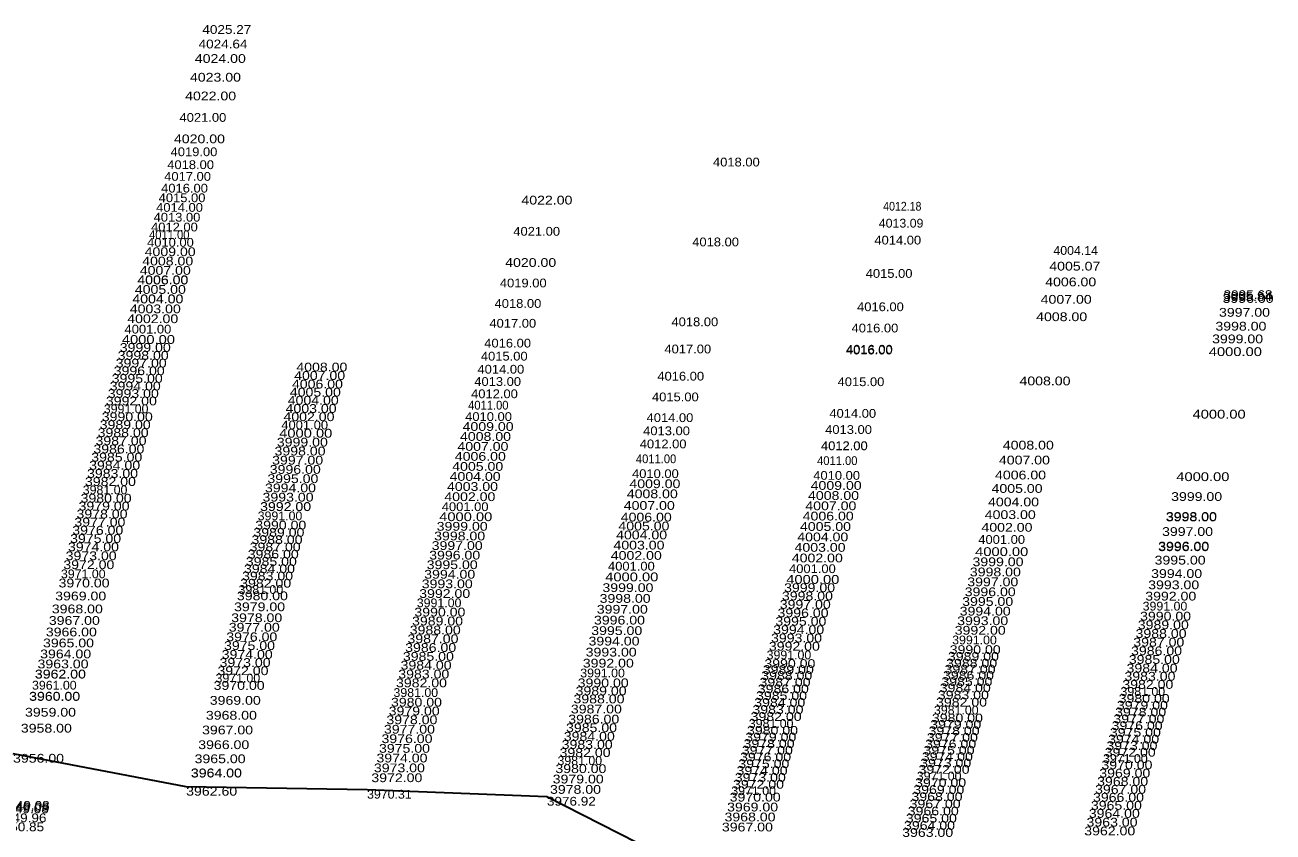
# Model space of a CAD drawing. Extents: x 49942 to 56479, y 47140 to 53283.
# Drawn here: x 54509 to 55219, y 49763 to 50222 of the extents above; entities that cross this region are included whole.
import ezdxf

# ---------------------------------------------------------------- set-up
doc = ezdxf.new("R2010")
doc.units = 0
doc.header["$LTSCALE"] = 2
doc.layers.add('29', color=7, linetype='Continuous')
doc.layers.add('59', color=7, linetype='Continuous', lineweight=35)

msp = doc.modelspace()

# ---------------------------------------------------------------- linework, layer by layer
at = {"layer": '59'}
for p, q in [((54600.525, 49789.026), (54502.081, 49807.794)), ((54703.403, 49787.333), (54600.525, 49789.026)), ((54805.688, 49783.359), (54703.403, 49787.333)), ((54896.947, 49736.929), (54805.688, 49783.359))]:
    msp.add_line(p, q, dxfattribs=at)

# ---------------------------------------------------------------- texts
at = {"layer": '29'}
for s, width, p in [('4025.27', 1.15, (54609.753, 50217.346)), ('4024.64', 1.15, (54607.606, 50209.081)), ('4024.00', 1.2, (54605.459, 50200.815)), ('4023.00', 1.2, (54602.694, 50190.169)), ('4022.00', 1.2, (54599.929, 50179.523)), ('4021.00', 1.1, (54596.759, 50167.32)), ('4020.00', 1.2, (54593.59, 50155.117)), ('4019.00', 1.1, (54591.683, 50147.774)), ('4018.00', 1.1, (54589.776, 50140.431)), ('4018.00', 1.1, (54900.119, 50141.93)), ('4017.00', 1.1, (54588.046, 50133.771)), ('4016.00', 1.1, (54586.309, 50127.085)), ('4015.00', 1.1, (54584.888, 50121.612)), ('4022.00', 1.2, (54791.18, 50120.288)), ('4013.00', 1.1, (54582.016, 50110.557)), ('4014.00', 1.1, (54583.466, 50116.138)), ('4012.18', 0.9, (54996.907, 50116.791)), ('4012.00', 1.1, (54580.567, 50104.976)), ('4013.09', 1.05, (54994.407, 50107.164)), ('4010.00', 1.1, (54578.3, 50096.247)), ('4011.00', 0.95, (54579.433, 50100.611)), ('4021.00', 1.1, (54786.568, 50102.532)), ('4018.00', 1.1, (54888.317, 50096.491)), ('4014.00', 1.1, (54991.907, 50097.538)), ('4009.00', 1.2, (54576.919, 50090.932)), ('4004.14', 1.05, (55093.696, 50091.652)), ('4008.00', 1.2, (54575.539, 50085.617)), ('4020.00', 1.2, (54781.956, 50084.776)), ('4005.07', 1.2, (55091.374, 50082.714)), ('4006.00', 1.2, (54572.73, 50074.803)), ('4006.00', 1.2, (54572.753, 50074.89)), ('4006.00', 1.2, (54572.775, 50074.978)), ('4007.00', 1.2, (54574.158, 50080.3)), ('4015.00', 1.1, (54986.982, 50078.579)), ('4005.00', 1.2, (54571.344, 50069.465)), ('4019.00', 1.1, (54778.934, 50073.142)), ('4006.00', 1.2, (55089.045, 50073.745)), ('4004.00', 1.2, (54569.931, 50064.025)), ('4004.00', 1.2, (54569.945, 50064.08)), ('4004.00', 1.2, (54569.957, 50064.128)), ('4018.00', 1.1, (54775.912, 50061.507)), ('4007.00', 1.2, (55086.473, 50063.842)), ('3996.00', 1.2, (55189.917, 50064.327)), ('3995.84', 1.15, (55190.2, 50065.42)), ('3995.68', 1.15, (55190.484, 50066.513)), ('4003.00', 1.2, (54568.474, 50058.416)), ('4016.00', 1.1, (54982.058, 50059.62)), ('4008.00', 1.2, (55083.9, 50053.938)), ('3997.00', 1.2, (55187.87, 50056.448)), ('4001.00', 1.1, (54565.485, 50046.91)), ('4002.00', 1.2, (54567.017, 50052.808)), ('4017.00', 1.1, (54772.983, 50050.229)), ('4018.00', 1.1, (54876.515, 50051.052)), ('4016.00', 1.1, (54978.918, 50047.529)), ('3998.00', 1.2, (55185.824, 50048.568)), ('4000.00', 1.25, (54563.954, 50041.013)), ('3999.00', 1.2, (55183.944, 50041.331)), ('3999.00', 1.2, (54562.773, 50036.466)), ('4016.00', 1.1, (54770.054, 50038.951)), ('4017.00', 1.1, (54872.501, 50035.598)), ('4016.00', 1.1, (54975.661, 50034.991)), ('4016.00', 1.1, (54975.719, 50035.215)), ('4016.00', 1.1, (54975.778, 50035.439)), ('4000.00', 1.25, (55182.064, 50034.093)), ('3997.00', 1.2, (54560.459, 50027.559)), ('3998.00', 1.2, (54561.592, 50031.92)), ('4008.00', 1.2, (54663.196, 50025.32)), ('4015.00', 1.1, (54768.124, 50031.518)), ('3995.00', 1.2, (54558.198, 50018.854)), ('3996.00', 1.2, (54559.327, 50023.198)), ('4007.00', 1.2, (54661.94, 50020.485)), ('4014.00', 1.1, (54766.193, 50024.086)), ('4016.00', 1.1, (54868.487, 50020.144)), ('3994.00', 1.2, (54557.07, 50014.51)), ('4005.00', 1.2, (54659.487, 50011.04)), ('4006.00', 1.2, (54660.684, 50015.651)), ('4013.00', 1.1, (54764.379, 50017.101)), ('4015.00', 1.1, (54970.984, 50016.982)), ('4008.00', 1.2, (55074.418, 50017.428)), ('3992.00', 1.2, (54554.872, 50006.047)), ('3993.00', 1.2, (54555.971, 50010.279)), ('4004.00', 1.2, (54658.289, 50006.428)), ('4011.00', 0.95, (54760.883, 50003.641)), ('4012.00', 1.1, (54762.565, 50010.116)), ('4015.00', 1.1, (54865.423, 50008.344)), ('3990.00', 1.2, (54552.541, 49997.072)), ('3991.00', 1.05, (54553.706, 50001.559)), ('4002.00', 1.2, (54655.859, 49997.071)), ('4003.00', 1.2, (54657.074, 50001.749)), ('4010.00', 1.1, (54759.198, 49997.155)), ('4014.00', 1.1, (54862.358, 49996.544)), ('4014.00', 1.1, (54966.306, 49998.974)), ('4000.00', 1.25, (55172.828, 49998.535)), ('3989.00', 1.2, (54551.366, 49992.55)), ('4001.00', 1.1, (54654.639, 49992.374)), ('4009.00', 1.2, (54757.729, 49991.499)), ('4013.00', 1.1, (54963.919, 49989.782)), ('3987.00', 1.2, (54548.984, 49983.376)), ('3988.00', 1.2, (54550.192, 49988.029)), ('3999.00', 1.2, (54652.101, 49982.605)), ('4000.00', 1.25, (54653.419, 49987.677)), ('4008.00', 1.2, (54756.26, 49985.843)), ('4013.00', 1.1, (54860.417, 49989.072)), ('3986.00', 1.2, (54547.775, 49978.722)), ('3998.00', 1.2, (54650.784, 49977.533)), ('4007.00', 1.2, (54754.79, 49980.181)), ('4012.00', 1.1, (54858.476, 49981.6)), ('4012.00', 1.1, (54961.506, 49980.489)), ('4012.00', 1.1, (54961.519, 49980.541)), ('4012.00', 1.1, (54961.532, 49980.591)), ('4008.00', 1.2, (55064.935, 49980.919)), ('3984.00', 1.2, (54545.363, 49969.437)), ('3985.00', 1.2, (54546.569, 49974.079)), ('3997.00', 1.2, (54649.429, 49972.315)), ('4005.00', 1.2, (54751.836, 49968.809)), ('4006.00', 1.2, (54753.319, 49974.52)), ('4011.00', 0.95, (54856.28, 49973.143)), ('4011.00', 0.95, (54959.325, 49972.094)), ('4007.00', 1.2, (55062.728, 49972.419)), ('3983.00', 1.2, (54544.163, 49964.816)), ('3995.00', 1.2, (54646.71, 49961.846)), ('3996.00', 1.2, (54648.074, 49967.097)), ('4004.00', 1.2, (54750.353, 49963.097)), ('4010.00', 1.1, (54854.083, 49964.686)), ('4010.00', 1.1, (54957.145, 49963.7)), ('4006.00', 1.2, (55060.52, 49963.92)), ('4000.00', 1.25, (55163.593, 49962.977)), ('3981.00', 1.05, (54541.732, 49955.455)), ('3982.00', 1.2, (54542.96, 49960.183)), ('3994.00', 1.2, (54645.345, 49956.593)), ('4003.00', 1.2, (54748.865, 49957.37)), ('4009.00', 1.2, (54852.594, 49958.953)), ('4009.00', 1.2, (54955.658, 49957.975)), ('4005.00', 1.2, (55058.53, 49956.259)), ('3980.00', 1.2, (54540.504, 49950.727)), ('3993.00', 1.2, (54643.972, 49951.305)), ('4002.00', 1.2, (54747.366, 49951.597)), ('4008.00', 1.2, (54851.105, 49953.219)), ('4008.00', 1.2, (54954.171, 49952.25)), ('4004.00', 1.2, (55056.539, 49948.593)), ('3999.00', 1.2, (55160.655, 49951.664)), ('3978.00', 1.2, (54538.176, 49941.764)), ('3979.00', 1.2, (54539.34, 49946.245)), ('3991.00', 1.05, (54641.208, 49940.664)), ('3992.00', 1.2, (54642.573, 49945.919)), ('3992.00', 1.2, (54642.585, 49945.967)), ('3992.00', 1.2, (54642.598, 49946.016)), ('4000.00', 1.25, (54744.409, 49940.215)), ('4001.00', 1.1, (54745.888, 49945.906)), ('4006.00', 1.2, (54847.665, 49939.977)), ('4007.00', 1.2, (54849.385, 49946.598)), ('4006.00', 1.2, (54951.135, 49940.561)), ('4007.00', 1.2, (54952.653, 49946.405)), ('4003.00', 1.2, (55054.664, 49941.373)), ('3998.00', 1.2, (55157.64, 49940.056)), ('3998.00', 1.2, (55157.675, 49940.191)), ('3998.00', 1.2, (55157.71, 49940.327)), ('3977.00', 1.2, (54536.973, 49937.132)), ('3990.00', 1.2, (54639.843, 49935.41)), ('3999.00', 1.2, (54742.983, 49934.723)), ('4005.00', 1.2, (54846.346, 49934.898)), ('4005.00', 1.2, (54949.594, 49934.628)), ('4002.00', 1.2, (55052.789, 49934.152)), ('3975.00', 1.2, (54534.541, 49927.77)), ('3976.00', 1.2, (54535.77, 49932.5)), ('3988.00', 1.2, (54637.701, 49927.16)), ('3989.00', 1.2, (54638.772, 49931.285)), ('3998.00', 1.2, (54741.556, 49929.23)), ('4004.00', 1.2, (54845.027, 49929.82)), ('4004.00', 1.2, (54948.053, 49928.695)), ('4001.00', 1.1, (55050.994, 49927.241)), ('3997.00', 1.2, (55155.484, 49931.754)), ('3974.00', 1.2, (54533.312, 49923.039)), ('3986.00', 1.2, (54635.551, 49918.883)), ('3987.00', 1.2, (54636.626, 49923.021)), ('3997.00', 1.2, (54740.142, 49923.783)), ('4003.00', 1.2, (54843.525, 49924.036)), ('4003.00', 1.2, (54946.509, 49922.749)), ('4000.00', 1.25, (55049.199, 49920.331)), ('3996.00', 1.2, (55153.244, 49923.133)), ('3996.00', 1.2, (55153.288, 49923.302)), ('3996.00', 1.2, (55153.327, 49923.452)), ('3972.00', 1.2, (54530.681, 49912.908)), ('3973.00', 1.2, (54531.997, 49917.973)), ('3985.00', 1.2, (54634.477, 49914.749)), ('3995.00', 1.2, (54737.314, 49912.895)), ('3996.00', 1.2, (54738.727, 49918.336)), ('4001.00', 1.1, (54840.417, 49912.071)), ('4002.00', 1.2, (54842.004, 49918.178)), ('4002.00', 1.2, (54944.945, 49916.728)), ('3999.00', 1.2, (55047.698, 49914.554)), ('3995.00', 1.2, (55151.26, 49915.495)), ('3971.00', 1.05, (54529.326, 49907.692)), ('3983.00', 1.2, (54632.332, 49906.489)), ('3984.00', 1.2, (54633.404, 49910.616)), ('3994.00', 1.2, (54735.901, 49907.455)), ('4000.00', 1.25, (54838.831, 49905.963)), ('4000.00', 1.25, (54941.779, 49904.539)), ('4001.00', 1.1, (54943.362, 49910.633)), ('3998.00', 1.2, (55046.198, 49908.778)), ('3994.00', 1.2, (55149.276, 49907.856)), ('3970.00', 1.2, (54527.972, 49902.477)), ('3981.00', 1.05, (54630.328, 49898.775)), ('3982.00', 1.2, (54631.26, 49902.362)), ('3993.00', 1.2, (54734.488, 49902.015)), ('3999.00', 1.2, (54837.242, 49899.844)), ('3999.00', 1.2, (54940.555, 49899.827)), ('3996.00', 1.2, (55043.264, 49897.481)), ('3997.00', 1.2, (55044.731, 49903.13)), ('3993.00', 1.2, (55147.612, 49901.448)), ('3969.00', 1.2, (54526.056, 49895.103)), ('3980.00', 1.2, (54629.396, 49895.188)), ('3991.00', 1.05, (54731.683, 49891.218)), ('3992.00', 1.2, (54733.052, 49896.489)), ('3998.00', 1.2, (54835.653, 49893.726)), ('3997.00', 1.2, (54938.09, 49890.335)), ('3998.00', 1.2, (54939.331, 49895.114)), ('3995.00', 1.2, (55041.834, 49891.977)), ('3992.00', 1.2, (55145.943, 49895.021)), ('3968.00', 1.2, (54524.141, 49887.729)), ('3979.00', 1.2, (54627.779, 49888.961)), ('3990.00', 1.2, (54730.314, 49885.946)), ('3997.00', 1.2, (54834.048, 49887.547)), ('3996.00', 1.2, (54936.83, 49885.484)), ('3994.00', 1.2, (55040.405, 49886.472)), ('3990.00', 1.2, (55142.988, 49883.646)), ('3991.00', 1.05, (55144.466, 49889.334)), ('3967.00', 1.2, (54522.44, 49881.178)), ('3977.00', 1.2, (54624.754, 49877.315)), ('3978.00', 1.2, (54626.162, 49882.735)), ('3989.00', 1.2, (54728.99, 49880.85)), ('3996.00', 1.2, (54832.443, 49881.369)), ('3994.00', 1.2, (54934.352, 49875.942)), ('3995.00', 1.2, (54935.591, 49880.713)), ('3993.00', 1.2, (55038.991, 49881.028)), ('3989.00', 1.2, (55141.704, 49878.702)), ('3966.00', 1.2, (54520.738, 49874.627)), ('3976.00', 1.2, (54623.347, 49871.895)), ('3987.00', 1.2, (54726.37, 49870.759)), ('3988.00', 1.2, (54727.667, 49875.754)), ('3994.00', 1.2, (54829.346, 49869.445)), ('3995.00', 1.2, (54830.895, 49875.407)), ('3993.00', 1.2, (54933.124, 49871.216)), ('3991.00', 1.05, (55036.149, 49870.086)), ('3992.00', 1.2, (55037.576, 49875.583)), ('3987.00', 1.2, (55139.142, 49868.837)), ('3988.00', 1.2, (55140.42, 49873.759)), ('3964.00', 1.2, (54517.497, 49862.147)), ('3965.00', 1.2, (54519.118, 49868.387)), ('3974.00', 1.2, (54620.744, 49861.874)), ('3975.00', 1.2, (54622.047, 49866.89)), ('3986.00', 1.2, (54725.072, 49865.764)), ('3993.00', 1.2, (54827.718, 49863.177)), ('3992.00', 1.2, (54931.897, 49866.49)), ('3990.00', 1.2, (55034.721, 49864.589)), ('3986.00', 1.2, (55137.864, 49863.916)), ('3963.00', 1.2, (54516.014, 49856.44)), ('3973.00', 1.2, (54619.538, 49857.231)), ('3984.00', 1.2, (54722.466, 49855.729)), ('3985.00', 1.2, (54723.769, 49860.747)), ('3992.00', 1.2, (54826.09, 49856.91)), ('3990.00', 1.2, (54929.342, 49856.656)), ('3991.00', 1.05, (54930.62, 49861.573)), ('3988.00', 1.2, (55032.723, 49856.896)), ('3989.00', 1.2, (55033.722, 49860.742)), ('3985.00', 1.2, (55136.586, 49858.997)), ('3962.00', 1.2, (54514.505, 49850.628)), ('3962.00', 1.2, (54514.519, 49850.682)), ('3962.00', 1.2, (54514.532, 49850.732)), ('3971.00', 1.05, (54617.244, 49848.398)), ('3972.00', 1.2, (54618.332, 49852.587)), ('3983.00', 1.2, (54721.158, 49850.694)), ('3991.00', 1.05, (54824.633, 49851.3)), ('3988.00', 1.2, (54927.572, 49849.839)), ('3989.00', 1.2, (54928.457, 49853.247)), ('3986.00', 1.2, (55030.923, 49849.967)), ('3987.00', 1.2, (55031.823, 49853.431)), ('3983.00', 1.2, (55134.103, 49849.434)), ('3984.00', 1.2, (55135.309, 49854.079)), ('3961.00', 1.05, (54512.878, 49844.362)), ('3970.00', 1.2, (54616.156, 49844.209)), ('3982.00', 1.2, (54719.85, 49845.658)), ('3989.00', 1.2, (54821.988, 49841.114)), ('3990.00', 1.2, (54823.176, 49845.69)), ('3986.00', 1.2, (54925.616, 49842.308)), ('3987.00', 1.2, (54926.599, 49846.092)), ('3984.00', 1.2, (55029.082, 49842.877)), ('3985.00', 1.2, (55030.002, 49846.422)), ('3981.00', 1.05, (55131.86, 49840.799)), ('3982.00', 1.2, (55132.896, 49844.789)), ('3960.00', 1.2, (54511.217, 49837.969)), ('3960.00', 1.2, (54511.233, 49838.03)), ('3960.00', 1.2, (54511.249, 49838.09)), ('3969.00', 1.2, (54613.954, 49835.73)), ('3980.00', 1.2, (54716.997, 49834.673)), ('3981.00', 1.05, (54718.423, 49840.166)), ('3988.00', 1.2, (54820.798, 49836.533)), ('3984.00', 1.2, (54923.593, 49834.518)), ('3985.00', 1.2, (54924.604, 49838.413)), ('3982.00', 1.2, (55026.962, 49834.717)), ('3983.00', 1.2, (55028.022, 49838.797)), ('3980.00', 1.2, (55130.824, 49836.809)), ('3959.00', 1.2, (54508.881, 49828.975)), ('3968.00', 1.2, (54611.752, 49827.252)), ('3979.00', 1.2, (54715.699, 49829.677)), ('3987.00', 1.2, (54819.313, 49830.814)), ('3982.00', 1.2, (54921.521, 49826.543)), ('3983.00', 1.2, (54922.557, 49830.531)), ('3981.00', 1.05, (55025.791, 49830.208)), ('3978.00', 1.2, (55128.819, 49829.09)), ('3979.00', 1.2, (55129.821, 49832.95)), ('3958.00', 1.2, (54506.525, 49819.904)), ('3977.00', 1.2, (54713.005, 49819.301)), ('3978.00', 1.2, (54714.402, 49824.681)), ('3985.00', 1.2, (54816.548, 49820.171)), ('3986.00', 1.2, (54817.819, 49825.065)), ('3981.00', 1.05, (54920.497, 49822.6)), ('3979.00', 1.2, (55023.675, 49822.062)), ('3980.00', 1.2, (55024.62, 49825.7)), ('3976.00', 1.2, (55126.813, 49821.369)), ('3977.00', 1.2, (55127.816, 49825.229)), ('3967.00', 1.2, (54609.578, 49818.885)), ('3976.00', 1.2, (54711.607, 49813.922)), ('3984.00', 1.2, (54815.277, 49815.277)), ('3979.00', 1.2, (54918.495, 49814.89)), ('3980.00', 1.2, (54919.473, 49818.657)), ('3977.00', 1.2, (55021.758, 49814.679)), ('3978.00', 1.2, (55022.731, 49818.425)), ('3974.00', 1.2, (55124.82, 49813.696)), ('3975.00', 1.2, (55125.821, 49817.548)), ('3966.00', 1.2, (54607.405, 49810.517)), ('3975.00', 1.2, (54710.18, 49808.427)), ('3982.00', 1.2, (54812.874, 49806.023)), ('3983.00', 1.2, (54814.075, 49810.65)), ('3977.00', 1.2, (54916.532, 49807.333)), ('3978.00', 1.2, (54917.516, 49811.123)), ('3975.00', 1.2, (55019.851, 49807.34)), ('3976.00', 1.2, (55020.785, 49810.933)), ('3972.00', 1.2, (55122.883, 49806.236)), ('3973.00', 1.2, (55123.851, 49809.966)), ('3956.00', 1.2, (54502.081, 49802.794)), ('3965.00', 1.2, (54605.323, 49802.5)), ('3974.00', 1.2, (54708.753, 49802.933)), ('3981.00', 1.05, (54811.686, 49801.452)), ('3975.00', 1.2, (54914.544, 49799.681)), ('3976.00', 1.2, (54915.547, 49803.543)), ('3973.00', 1.2, (55017.972, 49800.106)), ('3974.00', 1.2, (55018.918, 49803.746)), ('3970.00', 1.2, (55121.019, 49799.06)), ('3971.00', 1.05, (55121.952, 49802.652)), ('3964.00', 1.2, (54603.211, 49794.372)), ('3964.00', 1.2, (54603.227, 49794.43)), ('3964.00', 1.2, (54603.24, 49794.482)), ('3972.00', 1.2, (54705.841, 49791.72)), ('3973.00', 1.2, (54707.297, 49797.327)), ('3979.00', 1.2, (54808.967, 49790.981)), ('3980.00', 1.2, (54810.499, 49796.88)), ('3973.00', 1.2, (54912.524, 49791.902)), ('3974.00', 1.2, (54913.541, 49795.818)), ('3971.00', 1.05, (55016.048, 49792.696)), ('3972.00', 1.2, (55017.027, 49796.465)), ('3969.00', 1.2, (55119.797, 49794.355)), ('3962.60', 1.2, (54600.525, 49784.026)), ('3978.00', 1.2, (54807.435, 49785.082)), ('3971.00', 1.05, (54910.561, 49784.345)), ('3972.00', 1.2, (54911.507, 49787.986)), ('3969.00', 1.2, (55014.039, 49784.96)), ('3970.00', 1.2, (55015.069, 49788.927)), ('3967.00', 1.2, (55117.399, 49785.123)), ('3968.00', 1.2, (55118.575, 49789.65)), ('3970.31', 1.05, (54703.403, 49782.333)), ('3976.92', 1.15, (54805.688, 49778.359)), ('3970.00', 1.2, (54909.615, 49780.704)), ('3967.00', 1.2, (55011.938, 49776.872)), ('3968.00', 1.2, (55013.002, 49780.967)), ('3966.00', 1.2, (55116.223, 49780.595)), ('3949.08', 1.15, (54494.617, 49774.055)), ('3949.08', 1.15, (54494.868, 49775.022)), ('3949.08', 1.15, (54495.119, 49775.99)), ('3968.00', 1.2, (54906.677, 49769.393)), ('3969.00', 1.2, (54908.147, 49775.048)), ('3966.00', 1.2, (55010.874, 49772.776)), ('3964.00', 1.2, (55113.841, 49771.424)), ('3965.00', 1.2, (55115.032, 49776.009)), ('3950.85', 1.15, (54491.95, 49763.788)), ('3949.96', 1.15, (54493.283, 49768.921)), ('3967.00', 1.2, (54905.196, 49763.689)), ('3964.00', 1.2, (55008.751, 49764.6)), ('3965.00', 1.2, (55009.812, 49768.688)), ('3963.00', 1.2, (55112.546, 49766.438)), ('3963.00', 1.2, (55007.706, 49760.577)), ('3962.00', 1.2, (55111.251, 49761.452))]:
    msp.add_text(s, height=5, dxfattribs=dict(at, width=width)).set_placement(p)

doc.saveas('drawing.dxf')
